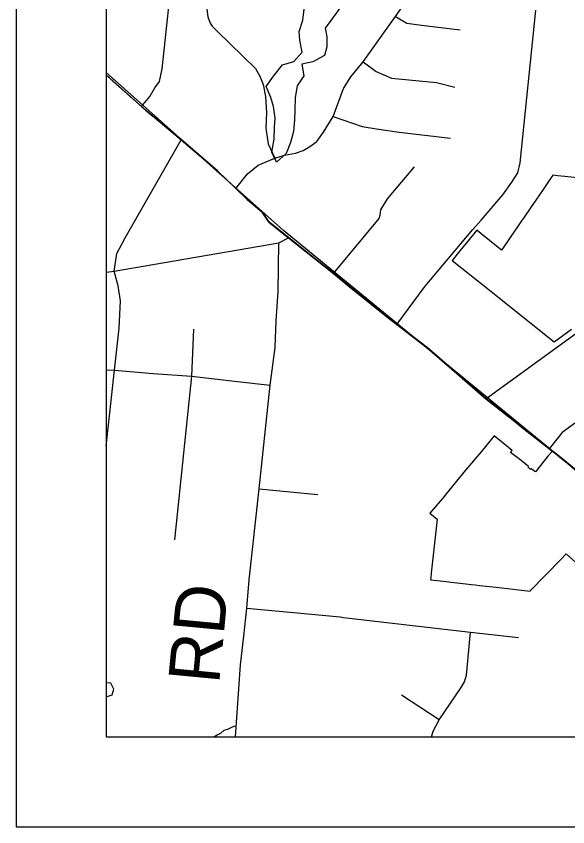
# Model space of a CAD drawing. Extents: x 0 to 34, y 0 to 22.
# Drawn here: x 2 to 2.613, y 14 to 14.902 of the extents above; entities that cross this region are included whole.
import ezdxf

# ---------------------------------------------------------------- set-up
doc = ezdxf.new("R2010")
doc.units = 0
for name, color, linetype in [('GM_X_Corporation', 7, 'Continuous'), ('GM_X_County_Road', 7, 'Continuous'), ('GM_X_Minor_Lake', 7, 'Continuous'), ('GM_X_Minor_River', 7, 'Continuous'), ('GM_X_Rail_Line', 7, 'Continuous'), ('GM_X_State_Route', 7, 'Continuous'), ('GM_X_Township_Road', 7, 'Continuous'), ('GM_X_Township_Road_Text', 7, 'Continuous'), ('SH_Data', 7, 'Continuous')]:
    doc.layers.add(name, color=color, linetype=linetype)

msp = doc.modelspace()

# ---------------------------------------------------------------- linework, layer by layer
at = {"layer": 'GM_X_Corporation'}
for points in [[(2.1, 16.09335), (2.1, 14.83652), (2.10765, 14.82948), (2.13895, 14.80151), (2.14343, 14.7975), (2.18303, 14.76477), (2.2238, 14.72961), (2.2438, 14.71033), (2.25666, 14.69822), (2.27252, 14.68471), (2.28053, 14.67317), (2.30256, 14.65557), (2.33094, 14.63288), (2.3526, 14.61594), (2.36977, 14.60157), (2.42293, 14.55904), (2.4567, 14.53311), (2.48953, 14.50475), (2.52206, 14.47655), (2.55083, 14.45401), (2.56126, 14.44542), (2.5973, 14.41705), (2.60788, 14.40877), (2.62061, 14.39819)], [(2.62061, 14.39819), (2.60788, 14.40877), (2.5973, 14.41705), (2.56126, 14.44542), (2.55083, 14.45401), (2.52206, 14.47655), (2.48953, 14.50475), (2.4567, 14.53311), (2.42293, 14.55904), (2.36977, 14.60157), (2.3526, 14.61594), (2.33094, 14.63288), (2.30256, 14.65557), (2.28053, 14.67317), (2.27252, 14.68471), (2.25666, 14.69822), (2.2438, 14.71033), (2.2238, 14.72961), (2.18303, 14.76477), (2.14343, 14.7975), (2.13895, 14.80151), (2.10765, 14.82948), (2.1, 14.83652), (2.1, 14.1), (2.92709, 14.1)], [(2.63408, 14.72059), (2.60982, 14.72319), (2.60182, 14.72404), (2.59652, 14.72461), (2.59399, 14.72093), (2.58568, 14.70878), (2.57758, 14.69696), (2.57164, 14.68828), (2.56401, 14.67713), (2.56191, 14.67407), (2.55664, 14.66638), (2.55146, 14.65881), (2.54614, 14.65104), (2.53951, 14.64135), (2.52611, 14.65213), (2.51656, 14.65982), (2.51196, 14.66352), (2.50023, 14.64906), (2.49338, 14.64061), (2.48474, 14.62997), (2.51514, 14.60575), (2.59822, 14.53956), (2.61719, 14.55336)], [(2.62189, 14.44944), (2.60692, 14.43841), (2.59817, 14.42733), (2.59304, 14.42083), (2.59655, 14.41798), (2.59632, 14.41769), (2.59629, 14.41766), (2.59104, 14.41206), (2.57726, 14.39483), (2.57555, 14.39594), (2.57519, 14.39617), (2.57234, 14.39804), (2.57232, 14.39802), (2.57192, 14.39745), (2.56914, 14.40004), (2.5695, 14.40057), (2.56121, 14.40753), (2.54936, 14.41645), (2.5512, 14.41871), (2.53132, 14.43479), (2.51708, 14.41696), (2.4996, 14.39655), (2.47808, 14.37035), (2.47598, 14.36786), (2.45988, 14.34872), (2.46801, 14.34199), (2.46139, 14.28214), (2.46139, 14.28214), (2.4608, 14.27678), (2.46056, 14.27462), (2.46804, 14.27378), (2.47817, 14.27265), (2.48666, 14.2717), (2.49991, 14.27023), (2.50569, 14.26959), (2.51033, 14.26907), (2.51494, 14.26856), (2.5337, 14.26647), (2.55261, 14.26437), (2.55562, 14.26404), (2.57134, 14.26222), (2.57139, 14.26228), (2.60599, 14.29781), (2.61151, 14.30348), (2.61152, 14.30346), (2.63996, 14.27817)]]:
    msp.add_lwpolyline(points, dxfattribs=at)
at = {"layer": 'GM_X_County_Road'}
msp.add_line((2.52229, 14.47602), (2.66473, 14.57966), dxfattribs=at)
msp.add_lwpolyline([(2.1, 14.61672), (2.10905, 14.61804), (2.29215, 14.64951), (2.3028, 14.65505)], dxfattribs=at)
at = {"layer": 'GM_X_Minor_Lake'}
msp.add_line((2.1052, 14.15985), (2.1, 14.15994), dxfattribs=at)
for points in [[(2.36061, 14.91149), (2.35088, 14.89836), (2.34348, 14.88822), (2.34522, 14.87869), (2.34541, 14.86766), (2.34258, 14.85783), (2.32991, 14.85083), (2.3177, 14.84838), (2.31976, 14.83542), (2.31235, 14.82415), (2.31023, 14.81126), (2.30961, 14.79721), (2.30942, 14.78619), (2.30844, 14.77328), (2.30481, 14.76118), (2.30004, 14.74872), (2.28923, 14.73941), (2.2841, 14.75052), (2.28662, 14.76492), (2.28724, 14.77859), (2.28778, 14.78808), (2.2861, 14.80104), (2.28323, 14.81135), (2.27773, 14.82322), (2.28592, 14.83487), (2.29602, 14.84761), (2.30863, 14.8512), (2.31793, 14.86168), (2.3155, 14.87502), (2.31452, 14.88454), (2.31853, 14.89701), (2.32027, 14.90953)], [(2.1, 14.14466), (2.1065, 14.1469), (2.1085, 14.15295), (2.1052, 14.15985)]]:
    msp.add_lwpolyline(points, dxfattribs=at)
at = {"layer": 'GM_X_Minor_River'}
msp.add_lwpolyline([(2.21967, 14.1), (2.22323, 14.1024), (2.22744, 14.10423), (2.2313, 14.10758), (2.23589, 14.10903), (2.24049, 14.11123), (2.24355, 14.11232)], dxfattribs=at)
at = {"layer": 'GM_X_Rail_Line'}
msp.add_lwpolyline([(2.92662, 14.1), (2.64317, 14.37918), (2.29707, 14.66316), (2.1, 14.8389)], dxfattribs=at)
at = {"layer": 'GM_X_State_Route'}
for points in [[(2.1, 14.83621), (2.10789, 14.82896), (2.13918, 14.80099), (2.18326, 14.76424), (2.22403, 14.72909), (2.24403, 14.70981), (2.2569, 14.69769), (2.27275, 14.68419), (2.28076, 14.67264), (2.3028, 14.65505), (2.33117, 14.63236), (2.35283, 14.61542), (2.37, 14.60105), (2.41534, 14.56477)], [(2.41534, 14.56477), (2.42316, 14.55852), (2.45693, 14.53259), (2.48976, 14.50423), (2.52229, 14.47602), (2.55106, 14.45349), (2.55427, 14.45085)], [(2.55427, 14.45085), (2.56149, 14.4449), (2.59507, 14.41846)], [(2.59507, 14.41846), (2.59753, 14.41653), (2.60811, 14.40825), (2.61111, 14.40576)], [(2.61111, 14.40576), (2.62084, 14.39766), (2.63112, 14.38877), (2.64231, 14.37941), (2.65464, 14.36727), (2.66302, 14.35901), (2.66747, 14.35426), (2.67675, 14.34604), (2.69714, 14.32577)]]:
    msp.add_lwpolyline(points, dxfattribs=at)
at = {"layer": 'GM_X_Township_Road'}
for p, q in [((2.27013, 14.37597), (2.33515, 14.36977)), ((2.47032, 14.11912), (2.42849, 14.14645))]:
    msp.add_line(p, q, dxfattribs=at)
for points in [[(2.28747, 14.74356), (2.29824, 14.74705), (2.31059, 14.7494), (2.31903, 14.75227), (2.32627, 14.75649), (2.33411, 14.76241), (2.34145, 14.7726), (2.35256, 14.79013), (2.36396, 14.82105), (2.372, 14.83405), (2.38572, 14.85087), (2.42153, 14.90135), (2.43334, 14.91751), (2.44736, 14.93271), (2.46466, 14.95153), (2.48168, 14.97384), (2.49542, 14.99988), (2.50714, 15.02475), (2.5146, 15.04358), (2.51902, 15.06745), (2.52135, 15.10078), (2.52426, 15.12735)], [(2.13918, 14.80099), (2.14873, 14.8123), (2.15399, 14.82184), (2.1593, 14.82906), (2.16232, 14.84303), (2.17534, 14.96415), (2.17763, 14.97927), (2.18003, 14.99425), (2.18679, 15.00745), (2.20044, 15.02574), (2.20407, 15.03368), (2.24524, 15.02755), (2.27195, 15.02431)], [(2.24524, 15.02755), (2.24477, 15.01892), (2.24272, 15.00508), (2.24069, 14.99717), (2.22183, 14.97775), (2.21805, 14.96706), (2.2146, 14.94036), (2.21334, 14.9248), (2.21193, 14.90955), (2.21303, 14.90092), (2.2157, 14.89385), (2.21774, 14.89039), (2.22387, 14.88473), (2.26618, 14.84335), (2.27098, 14.83485), (2.27443, 14.82555), (2.27701, 14.81211), (2.27832, 14.79424), (2.27744, 14.77692), (2.28008, 14.75961), (2.28747, 14.74356)], [(2.5168, 14.67484), (2.54101, 14.70289), (2.55118, 14.71713), (2.5575, 14.72751), (2.56014, 14.7385), (2.57784, 14.90821)], [(2.42153, 14.90135), (2.43411, 14.89384), (2.45055, 14.89154), (2.49362, 14.88628)], [(2.38572, 14.85087), (2.4001, 14.84002), (2.41729, 14.83257), (2.4673, 14.82769), (2.48774, 14.82248)], [(2.35256, 14.79013), (2.38479, 14.77877), (2.40058, 14.77614), (2.42589, 14.77252), (2.48277, 14.76595)], [(2.10905, 14.61804), (2.11181, 14.63764), (2.12112, 14.65515), (2.18326, 14.76424)], [(2.24403, 14.70981), (2.25714, 14.72614), (2.26901, 14.73582), (2.28747, 14.74356)], [(2.35283, 14.61542), (2.40355, 14.67642), (2.40447, 14.68033), (2.4053, 14.68618), (2.41289, 14.69846), (2.4429, 14.73391)], [(2.42316, 14.55852), (2.45457, 14.60142), (2.50764, 14.66423), (2.5168, 14.67484)], [(2.24374, 14.1), (2.24948, 14.18009), (2.25307, 14.21184), (2.25645, 14.24312), (2.25888, 14.27471), (2.27013, 14.37597), (2.28237, 14.49118), (2.2879, 14.53322), (2.28906, 14.56263), (2.29138, 14.59553), (2.29215, 14.64951)], [(2.1, 14.42326), (2.10917, 14.50785), (2.11453, 14.55462), (2.11597, 14.5851), (2.11337, 14.60178), (2.10905, 14.61804)], [(2.19716, 14.55362), (2.19477, 14.5013), (2.176, 14.31928)], [(2.1, 14.50825), (2.10917, 14.50785), (2.15244, 14.50412), (2.19477, 14.5013), (2.24617, 14.49525), (2.28237, 14.49118)], [(2.25645, 14.24312), (2.36002, 14.23335), (2.36391, 14.23289)], [(2.36391, 14.23289), (2.50508, 14.21637), (2.55852, 14.21055)], [(2.46188, 14.1), (2.46208, 14.10124), (2.46369, 14.10626), (2.4669, 14.11269), (2.47032, 14.11912), (2.49483, 14.15509), (2.49845, 14.16112), (2.50046, 14.16875), (2.50508, 14.21637)]]:
    msp.add_lwpolyline(points, dxfattribs=at)
at = {"layer": 'SH_Data'}
for p, q in [((2, 21), (2, 14)), ((2.1, 20.9), (2.1, 14.1)), ((2.1, 14.1), (8.9, 14.1)), ((2.1, 14.1), (2.1, 14.1)), ((2, 14), (9, 14))]:
    msp.add_line(p, q, dxfattribs=at)

# ---------------------------------------------------------------- texts
at = {"layer": 'GM_X_Township_Road_Text'}
msp.add_text('RD', height=0.056818, rotation=84.58971, dxfattribs=at).set_placement((2.2255, 14.15787))

doc.saveas('drawing.dxf')
